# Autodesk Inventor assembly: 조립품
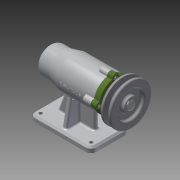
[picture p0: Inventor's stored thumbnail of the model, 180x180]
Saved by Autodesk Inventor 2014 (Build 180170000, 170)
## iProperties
Created: 2019-07
Part Number: 조립품
Document SubType Name: Assembly
Designer: kh
Author: kh
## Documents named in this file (12)
- C:\Users\kh\Desktop\490704v1073\조립품.iam
- C:\Users\kh\Desktop\490704v1073\본체.ipt
- C:\Users\kh\Desktop\490704v1073\베어링 6004.ipt
- C:\Users\kh\Desktop\490704v1073\베어링 51202.ipt
- C:\Users\kh\Desktop\490704v1073\어댑터슬리브.ipt
- C:\Users\kh\Desktop\490704v1073\축.ipt
- C:\Users\kh\Desktop\490704v1073\볼트 M4.ipt
- C:\Users\kh\Desktop\490704v1073\V벨트풀리.ipt
- C:\Users\kh\Desktop\490704v1073\커버.ipt
- C:\Users\kh\Desktop\490704v1073\키 5 x 5 x 16.ipt
- C:\Users\kh\Desktop\490704v1073\오일 실.ipt
- C:\Users\kh\Desktop\490704v1073\멈춤나사 M3.ipt
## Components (1 placed, 1 different names)
1. V벨트풀리:1 — Mate:22, Mate:23, Flush:1, Flush:2
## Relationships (4: Mate 2, Flush 2)
- Mate:22: V벨트풀리:1
- Mate:23: V벨트풀리:1
- Flush:1: V벨트풀리:1
- Flush:2: V벨트풀리:1
